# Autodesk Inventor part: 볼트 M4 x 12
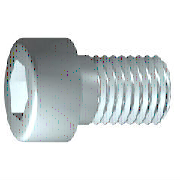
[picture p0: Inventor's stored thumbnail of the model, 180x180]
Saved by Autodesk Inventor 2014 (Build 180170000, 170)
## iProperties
IsCustomPart: 0
Created: 2012-02
Part Number: 볼트 M4 x 12
Material: 스테인리스강
Description: 6각 소켓 머리 캡 나사
Document SubType Name: Modeling
Standard: ISO 4762
Designer: mduedu
Standard Revision: Fourth edition 2004-03-01
Standards Organization: ISO
Language: ko-KR
Size Designation: M4 x 12
Categories: <MemberInstance><Categories><Category DisplayName="조임쇠" InternalName="e4da775c-781d-43d5-af7c-5136215cf5a6" Mnemonic="FSTN"><Category DisplayName="볼트" InternalN
Density: 8.08 g/cm^3
Appearance: 기본값
Author: mduedu
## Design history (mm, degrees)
sketch "스케치1"
  geometry: L1 (-1, 0)-(12, 0); L2 (12, 0)-(12, 2); L3 (12, 2)-(1.75, 2); L4 (1.75, 2)-(1.32, 2); L5 (1.32, 2)-(0, 2); L6 (0, 2)-(0, 3.5); L7 (0, 3.5)-(-4, 3.5); L8 (-4, 3.5)-(-4, 1.732); L9 (-4, 1.732)-(-2, 1.732); L10 (-2, 1.732)-(-1, 0); L11 (-7.2, 0)-(15.2, 0) reference; L12 (0, -0.7)-(0, 4.2) reference; L13 (1.75, 2)-(0, 2)
  constraints: 22 end point, 6 parallel, 2 collinear, 2 perpendicular, 1 horizontal, 1 point on line
  dimensions: "d1" = 10.25 distance from line of L3.end L2 (= GEL); "d2" = 0.42952 distance of L4.end L3.end (computed from GAL); "d3" = 4 distance between parallel lines of L8 L6 (= KOH); "d4" = 2 distance of L8.end L9.end (= INTI); "d5" = 60 deg angle of L10 L1; "d6" = 4 diameter of L3 L1 (= GD); "d7" = 4 diameter of L5 L1 (= BDM); "d8" = 3.4641 diameter of L9 L1 (= 1.1547 x SW); "d9" = 7 diameter of L7 L1 (= KOD); "d26" = 12 distance between parallel lines of L12 L2 (= NLG)
revolve "본체" sketch "스케치1" stored, may be unused: angle "d10" = 90 deg
sketch "스케치2"
  geometry: L1 (0, -4.9)-(0, 4.9) reference; L2 (-4.9, 0)-(4.9, 0) reference; L3 (1.732, 0)-(0.866, -1.5); L4 (0.866, -1.5)-(-0.866, -1.5); L5 (-0.866, -1.5)-(-1.732, 0); L6 (-1.732, 0)-(-0.866, 1.5); L7 (-0.866, 1.5)-(0.866, 1.5); L8 (0.866, 1.5)-(1.732, 0); 2 further points
  constraints: 12 end point, 1 coincident, 1 horizontal alignment, 1 point on line, 12 other
extrude "슬롯" join sketch "스케치2" stored distance "d11" = 10; taper "d12" = 0 deg
workplane "Work Plane1"
fillet "Fillet2" dims "d30" = 0.1 (= R)
body "Solid1"
fillet "모깎기1" dims "d17" = 0.4 (= RR)
feature "스레드" dims "d13" = 10.25 (= GEL), "d14" = 0
chamfer "모따기1" distance "d15" = 0.42941 (= -0.5 x SPD + 0.5 x GD); stored, may be unused: second distance "d16" = 0.42941 (= GUL), angle "d27" = 45 deg
other parameters: "GD" = 4 [user parameter; used in 2 equation terms], "NLG" = 12 [user parameter; used in 1 equation term], "GEL" = 10.25 [user parameter; used in 2 equation terms], "KOD" = 7 [user parameter; used in 1 equation term], "KOH" = 4 [user parameter; used in 1 equation term], "INTI" = 2 [user parameter; used in 1 equation term], "GAL" = 0.42941 (= 0.61345 x PTC) [user parameter; used in 1 equation term], "GUL" = 0.42941 (= 0.61345 x PTC) [user parameter; used in 1 equation term], "BDM" = 4 (= NND) [user parameter; used in 1 equation term], "SW" = 3 [user parameter; used in 2 equation terms], "RR" = 0.4 [user parameter; used in 1 equation term], "SPD" = 3.14117 (= NND - 1.2269 x PTC) [user parameter; used in 1 equation term], "d19" = 0, "d28" = 0, "d29" = 0, "R" = 0.1 [user parameter; used in 1 equation term], "TOA" = 30 deg [user parameter], "GD1" = 3.14117 (= THREADDIA - 1.2269 x PTC) [user parameter], "THREADDIA" = 4 [user parameter; used in 1 equation term], "FAWI" = 45 deg [user parameter], "TPU" = 14.28571 (computed from PTC) [user parameter], "PTC" = 0.7 [user parameter; used in 5 equation terms], "NND" = 4 [user parameter; used in 2 equation terms], "E0" = 3.465 (= 1.155 x SW) [user parameter]
